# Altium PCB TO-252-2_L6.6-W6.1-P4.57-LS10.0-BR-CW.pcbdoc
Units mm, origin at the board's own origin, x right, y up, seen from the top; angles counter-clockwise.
Board outline 23.93 x 19.36 mm, 2 copper layers (Top Layer, Bottom Layer), stack 0 mm thick; 1 components, 0 nets, 3 pads, 0 vias.
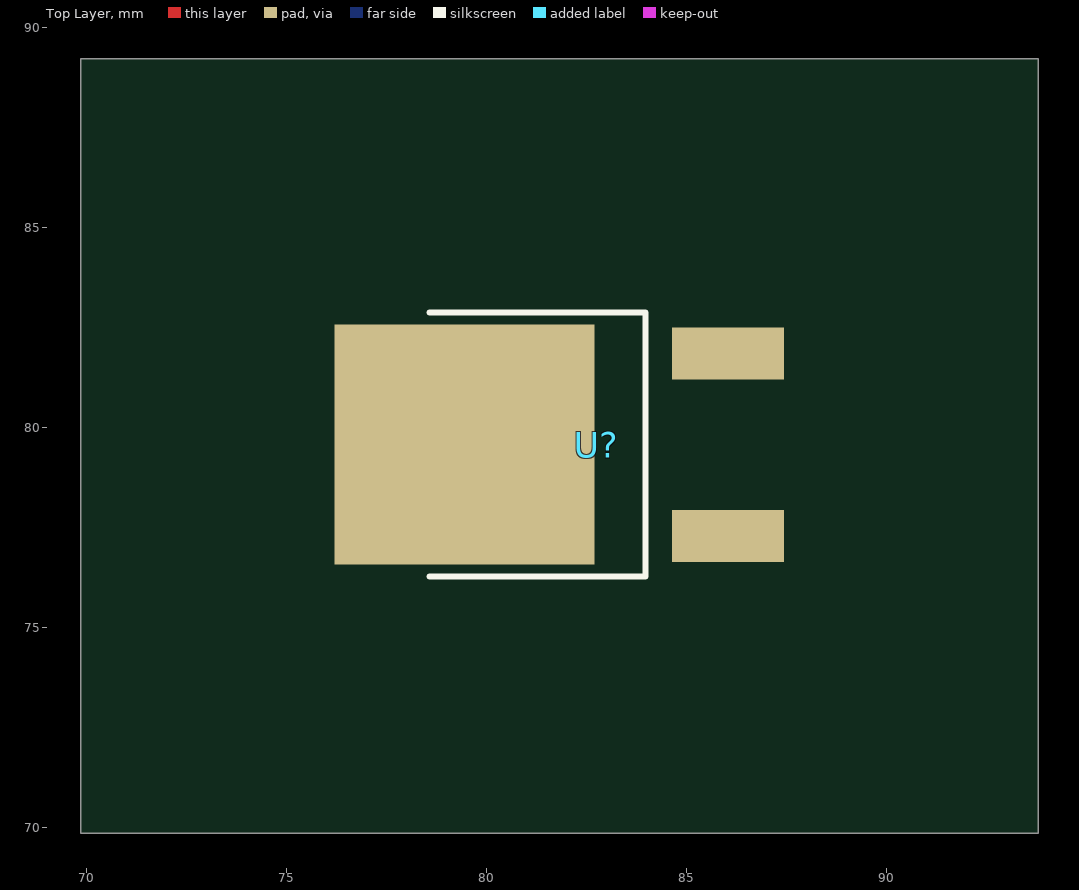
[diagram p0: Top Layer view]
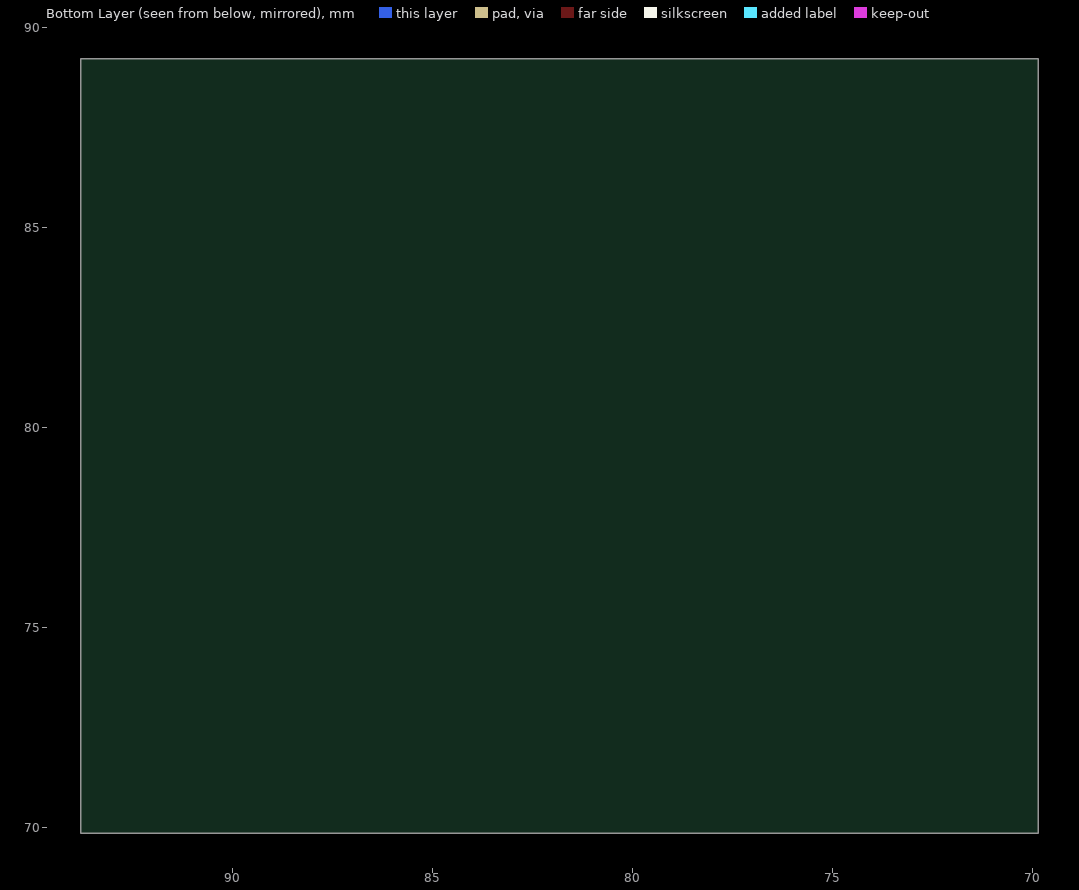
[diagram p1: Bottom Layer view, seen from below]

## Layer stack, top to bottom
Top Layer: signal copper (thickness not stored)
Bottom Layer: signal copper (thickness not stored)

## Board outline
93.784,69.85 69.85,69.85 69.85,89.21 93.784,89.21

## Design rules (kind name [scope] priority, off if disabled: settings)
PasteMaskExpansion "Paste Mask Expansion" [All] p1: expansion=0
SolderMaskExpansion "Solder Mask Expansion" [IsVia] p1: expansion=-25.4 istentingtop=TRUE
SolderMaskExpansion "Solder Mask Expansion" [All] p2: expansion=0.051 istentingtop=FALSE

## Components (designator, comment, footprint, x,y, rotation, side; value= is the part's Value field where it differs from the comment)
U? "" TO-252-2_L6.6-W6.1-P4.57-LS10.0-BR-CW 82.742,79.56 r0 top

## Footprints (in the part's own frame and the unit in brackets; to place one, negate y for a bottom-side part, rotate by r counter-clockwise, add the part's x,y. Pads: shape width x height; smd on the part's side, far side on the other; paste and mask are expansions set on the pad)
TO-252-2_L6.6-W6.1-P4.57-LS10.0-BR-CW [mm]
  rect 2.8x1.3 smd: 1(3.292,-2.285) 3(3.292,2.285)
  rect 6.5x6 smd: 2(-3.292,0)
  silkscreen extent -4.17,-3.3 1.23,3.3

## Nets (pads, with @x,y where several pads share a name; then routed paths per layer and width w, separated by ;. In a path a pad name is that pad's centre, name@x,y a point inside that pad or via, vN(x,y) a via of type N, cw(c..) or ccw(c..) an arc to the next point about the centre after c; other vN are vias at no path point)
pads on no net: U?.1 U?.2 U?.3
